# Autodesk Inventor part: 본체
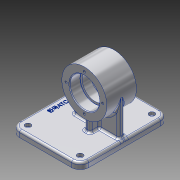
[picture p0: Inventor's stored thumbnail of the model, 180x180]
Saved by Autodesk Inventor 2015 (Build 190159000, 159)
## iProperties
Created: 2019-09
Part Number: 본체
Material: 알루미늄 6061
Document SubType Name: Modeling
Designer: LINEART-SSD.D4.16.07
Density: 2.7 g/cm^3
Appearance: 알루미늄 - 평지
Mass: 551.855 g
Surface Area: 493.273 cm^2
Volume: 204.391 cm^3
Author: LINEART-SSD.D4.16.07
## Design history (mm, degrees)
sketch "스케치1"
  geometry: L1 (49, 63)-(-49, 63); L2 (-49, 63)-(-49, -63); L3 (-49, -63)-(49, -63); L4 (49, -63)-(49, 63); 1 further point
  constraints: 8 end point, 2 parallel, 1 horizontal, 1 perpendicular
  dimensions: "d0" = 126 distance of L3.end L1.start; "d1" = 63 distance from line of L3 point (0, 0); "d2" = 98 distance of L2.end L3.end; "d3" = 49 distance from line of point (0, 0) L4
extrude "돌출1" new body sketch "스케치1" distance "d4" = 9; taper "d5" = 0 deg
sketch "스케치2"
  geometry: L1 (49, 0)-(49, 9) reference; C1 r 32 at (13, 59); 1 further point
  constraints: 1 centre point
  dimensions: "d6" = 32 radius of C1; "d8" = 36 distance from line of L1 C1.centre; "d62" = 59 vertical distance of point (0, 0) C1.centre
extrude "돌출2" join sketch "스케치2" stored distance "d9" = 42; taper "d10" = 0 deg
sketch "스케치3"
  geometry: L1 (-19, 59)-(45, 59); L2 (45, 59)-(45, 0); L3 (45, 0)-(-19, 0); L4 (-19, 0)-(-19, 59); L5 (49, 0)-(-49, 0) reference; L6 (-49, 0)-(-49, 9) reference; L7 (49, 9)-(-49, 9) reference; L8 (49, 0)-(49, 9) reference; C1 r 32 at (13, 59) reference; 3 further points
  constraints: 8 end point, 2 midpoint, 2 parallel, 1 coincident, 1 horizontal, 1 horizontal alignment, 1 perpendicular, 1 vertical alignment
  dimensions: "d11" = 64 distance of L2.end L3.end
extrude "돌출3" join sketch "스케치3" stored distance "d12" = 8; taper "d13" = 0 deg
node "작업 평면1"
sketch "스케치4"
  geometry: L1 (32.408, 17)-(0, 17); L2 (0, 17)-(0, -17); L3 (0, -17)-(32.408, -17); L4 (32.408, -17)-(32.408, 17); 1 further point
  constraints: 8 end point, 2 parallel, 1 horizontal, 1 perpendicular, 1 vertical alignment
  dimensions: "d15" = 17 distance from line of L3 point (0, 0); "d16" = 34 distance of L1.end L2.end; "d17" = 32.40772 distance of L2.end L3.end
extrude "돌출4" join sketch "스케치4" stored distance "d18" = 8; taper "d19" = 0 deg
sketch "스케치5"
  geometry: C1 r 32 at (0, 0) reference; C2 r 21 at (0, 0); 1 further point
  constraints: 1 centre point, 1 coincident
  dimensions: "d20" = 21 radius of C2
extrude "돌출5" cut sketch "스케치5" distance "d21" = 15; taper "d22" = 0 deg
sketch "스케치6"
  geometry: C1 r 21 at (0, 0) reference; C2 r 32 at (0, 0) reference; C3 r 21 at (0, 0); 1 further point
  constraints: 1 centre point, 1 coincident
  dimensions: "d23" = 21 radius of C3
extrude "돌출6" cut sketch "스케치6" distance "d24" = 15; taper "d25" = 0 deg
sketch "스케치7"
  geometry: C1 r 21 at (0, 0) reference; C2 r 32 at (0, 0) reference; C3 r 18 at (0, 0); 1 further point
  constraints: 1 centre point, 1 coincident
  dimensions: "d26" = 18 radius of C3
extrude "돌출7" cut sketch "스케치7" stored distance "d27" = 15; taper "d28" = 0 deg
sketch "스케치8"
  geometry: C1 r 21 at (0, 0) reference; C2 r 32 at (0, 0) reference; 2 further points
  constraints: 1 vertical alignment
  dimensions: "d29" = 26 distance of point (0, 26) C1.centre
hole "구멍1" sketch "스케치8" at (0, 26) diameter "d30" = 3.242; stored, may be unused: countersink angle "d34" = 90 deg, drill point angle "d36" = 118 deg; dims "d31" = 8, "d32" = 4, "d33" = 2, "d35" = 10
sketch "스케치9"
  geometry: L1 (-49, -63)-(49, -63) reference; L2 (-49, 63)-(-49, -63) reference; L3 (49, 63)-(-49, 63) reference; L4 (49, -63)-(49, 63) reference; 5 further points
  constraints: 2 horizontal alignment, 2 vertical alignment
  dimensions: "d40" = 12 distance from line of point (-37, -51) L1; "d41" = 12 distance from line of L2 point (-37, -51); "d42" = 12 distance from line of L4 point (37, -51); "d43" = 12 distance from line of L3 point (37, 51)
hole "구멍2" sketch "스케치9" at (-37, -51), (37, -51), (37, 51), (-37, 51) diameter "d44" = 4.5; stored, may be unused: countersink angle "d48" = 90 deg, drill point angle "d50" = 118 deg; dims "d45" = 8, "d46" = 8, "d47" = 4.4, "d49" = 10
fillet "모깎기1" dims "d51" = 0.3, "d52" = 12, "d53" = 3
fillet "모깎기2" dims "d54" = 3
sketch "스케치10"
  geometry: L1 (-49, 51)-(-49, -51) reference; L2 (37, 63)-(-37, 63) reference; 2 further points
  constraints: 1 other
  dimensions: "d55" = 10 distance from line of point (-39, 0) L1; "d56" = 63 distance from line of point (-39, 0) L2
feature "엠보싱1" sketch "스케치10" dims "d0" = 126, "d1" = 63, "d2" = 98, "d3" = 49, "d57" = 0.5, "d58" = 0
chamfer "모따기1" distance "d59" = 1; stored, may be unused: second distance "d60" = 2, angle "d61" = 45 deg
node "솔리드1"
pattern_circular "원형 패턴1" dims angle "d38" = 360 deg
mirror "대칭1"
node "투영된 루프1"
node "투영된 루프2"
node "투영된 루프3"
node "투영된 루프4"
node "투영된 루프5"
node "투영된 루프6"
node "투영된 루프7"
other parameters: "d14" = 13
